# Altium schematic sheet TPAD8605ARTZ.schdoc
size 127 x 101 mm
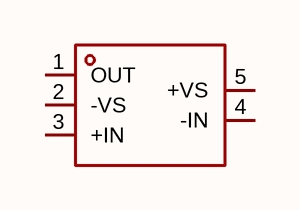
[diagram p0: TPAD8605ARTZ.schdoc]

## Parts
U?  tpad8605artz  [SOT-23-5_L2.9-W1.6-P0.95-LS2.8-BL]  (value not drawn)

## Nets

Not connected (* = marked no-connect by the designer): U? 1(OUT) 2(-VS) 3(+IN) 4(-IN) 5(+VS)

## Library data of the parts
U? = tpad8605artz: 放大器数:1;轨到轨:轨到轨输入,轨到轨输出;增益带宽积(GBW):10MHz;输入失调电压(Vos):5mV;压摆率(SR):4.5V/us;输入偏置电流(Ib):10pA;; Manufacturer: TECH PUBLIC(台舟); AddInBom: yes; ModelId: 018c57e721114987ae90467fe9f1d259; ModelTransform: 114.96,110.236,0,0,0,0,0,0,0; Number of Channels: 1; Maximum Power Supply Range (Vdd-Vss): 7V; Gain Bandwidth Product: 10MHz; Vos - Input Offset Voltage: 5mV; Input Offset Voltage Drift(Vos TC): 1.5uV/℃; Ib - Input Bias Current: 10pA; Input Offset Current(Ios): 100pA; Input Voltage Noise Density: 15nV/√Hz@30kHz; Common Mode Rejection Ratio(CMRR): 80dB; Quiescent Current: 800uA; Output Current: 50mA; Single supply: 2.2V~5.5V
